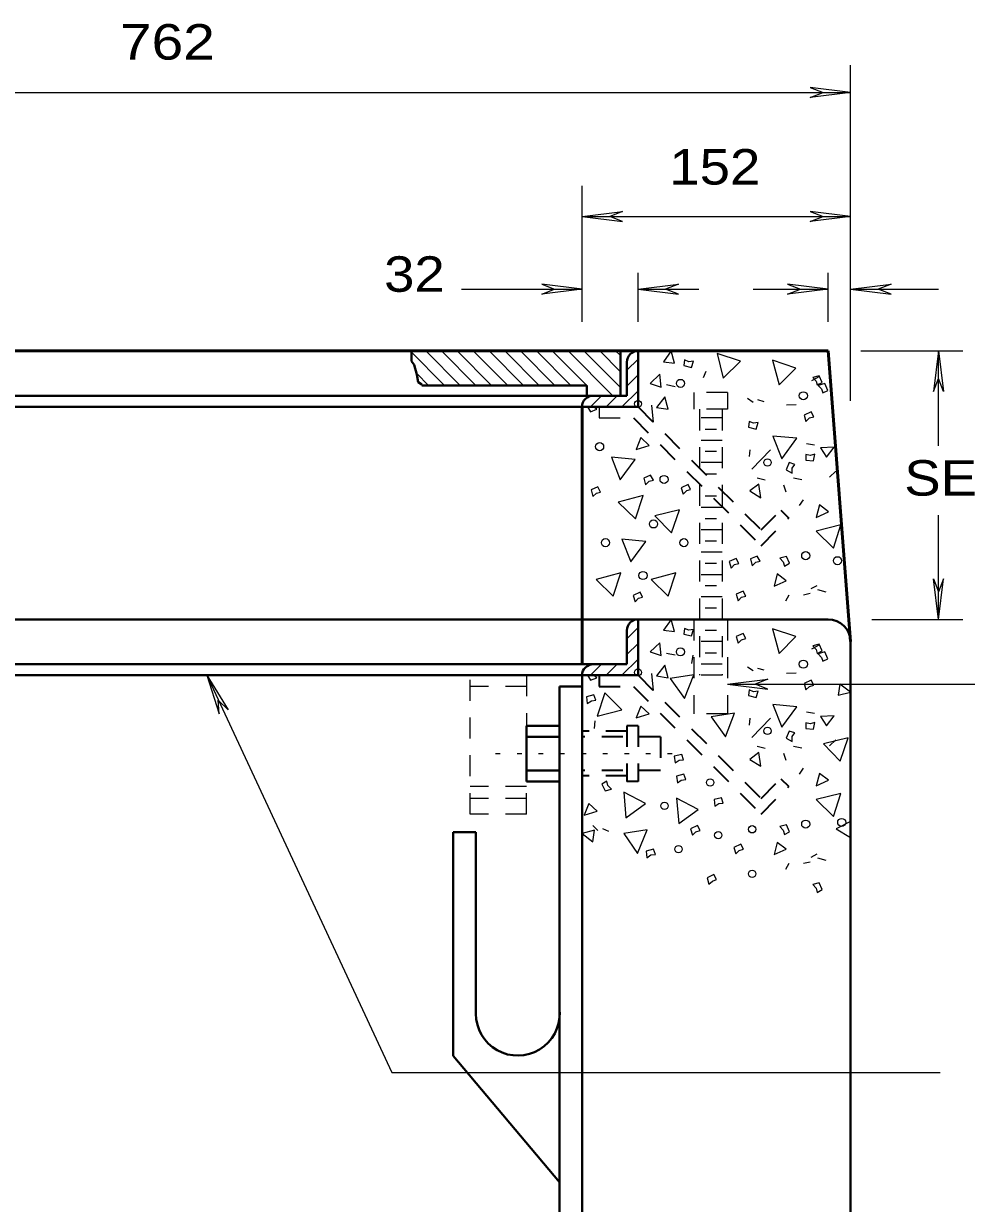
# Model space of a CAD drawing. Extents: x 312583 to 312853, y 144419 to 144586.
# Drawn here: x 312765.66 to 312785.86, y 144474.02 to 144499.29 of the extents above; entities that cross this region are included whole.
import ezdxf

# ---------------------------------------------------------------- set-up
doc = ezdxf.new("R2010")
doc.units = 0
doc.header["$LTSCALE"] = 0.3
doc.header["$PDMODE"] = 32
doc.header["$PDSIZE"] = 0.15
doc.linetypes.add('DOTTED', pattern=[1.5, 0.3, -1.2])
doc.linetypes.add('SHORT_DASHED', pattern=[2.7, 1.5, -1.2])
doc.layers.add('1', color=7, linetype='Continuous', lineweight=40)
doc.layers.add('2', color=7, linetype='Continuous', lineweight=13)

msp = doc.modelspace()

# ---------------------------------------------------------------- linework, layer by layer
at = {"layer": '1', "lineweight": 53}
for p, q in [((312755.1014, 144492.2754), (312782.893, 144492.2754)), ((312783.376, 144486.0501), (312782.893, 144492.2754)), ((312777.626, 144491.0794), (312777.626, 144485.5671))]:
    msp.add_line(p, q, dxfattribs=at)
at = {"layer": '1'}
for p, q in [((312778.4464, 144492.2754), (312778.4464, 144491.3171)), ((312778.822, 144492.2754), (312778.822, 144491.0794)), ((312778.5844, 144492.0377), (312778.5844, 144491.3171)), ((312774.1914, 144491.5394), (312777.7257, 144491.5394)), ((312777.7257, 144491.5394), (312777.7257, 144491.3171)), ((312759.4177, 144491.3171), (312778.5844, 144491.3171)), ((312759.18, 144491.0794), (312778.822, 144491.0794)), ((312755.1014, 144486.5254), (312782.893, 144486.5254)), ((312778.5844, 144486.2877), (312778.5844, 144485.5671)), ((312778.822, 144486.5254), (312778.822, 144485.3294)), ((312783.376, 144486.0501), (312783.376, 144443.4004)), ((312759.295, 144485.5671), (312778.5844, 144485.5671)), ((312759.0574, 144485.3294), (312778.822, 144485.3294)), ((312777.626, 144485.3294), (312777.626, 144443.4004)), ((312777.626, 144485.0917), (312777.143, 144485.0917)), ((312777.143, 144485.0917), (312777.143, 144454.4251)), ((312776.43, 144484.2484), (312776.43, 144483.0524)), ((312777.143, 144484.2484), (312776.43, 144484.2484)), ((312777.143, 144484.0107), (312776.43, 144484.0107)), ((312777.143, 144483.2901), (312776.43, 144483.2901)), ((312777.143, 144483.0524), (312776.43, 144483.0524)), ((312774.866, 144481.9714), (312774.866, 144477.1797)), ((312775.349, 144481.9714), (312774.866, 144481.9714)), ((312775.349, 144481.9714), (312775.349, 144478.0844)), ((312777.143, 144474.4734), (312774.866, 144477.1797))]:
    msp.add_line(p, q, dxfattribs=at)
at = {"layer": '1', "linetype": 'SHORT_DASHED', "lineweight": 25}
for p, q in [((312780.018, 144491.3861), (312780.018, 144491.0257)), ((312780.7387, 144491.3861), (312780.018, 144491.3861)), ((312780.7387, 144491.3861), (312780.7387, 144491.0257)), ((312777.9864, 144491.0794), (312777.9864, 144490.8417)), ((312777.9864, 144490.8417), (312778.7224, 144490.8417)), ((312780.7387, 144491.0257), (312780.018, 144491.0257)), ((312780.1407, 144491.0257), (312780.1407, 144485.3294)), ((312780.6237, 144490.8417), (312780.1407, 144490.8417)), ((312780.6237, 144491.0257), (312780.6237, 144485.3294)), ((312780.501, 144490.5964), (312780.2634, 144490.5964)), ((312780.6237, 144490.3587), (312780.1407, 144490.3587)), ((312780.501, 144490.1211), (312780.2634, 144490.1211)), ((312780.6237, 144489.8834), (312780.1407, 144489.8834)), ((312780.501, 144489.6381), (312780.2634, 144489.6381)), ((312780.501, 144489.1627), (312780.2634, 144489.1627)), ((312780.6237, 144488.9251), (312780.1407, 144488.9251)), ((312780.501, 144488.6797), (312780.2634, 144488.6797)), ((312780.6237, 144488.4421), (312780.1407, 144488.4421)), ((312780.501, 144488.2044), (312780.2634, 144488.2044)), ((312780.6237, 144487.9667), (312780.1407, 144487.9667)), ((312780.501, 144487.7214), (312780.2634, 144487.7214)), ((312780.6237, 144487.4837), (312780.1407, 144487.4837)), ((312780.501, 144487.2461), (312780.2634, 144487.2461)), ((312780.6237, 144487.0084), (312780.1407, 144487.0084)), ((312780.501, 144486.7631), (312780.2634, 144486.7631)), ((312780.018, 144486.5254), (312780.018, 144484.5014)), ((312780.6237, 144486.5254), (312780.1407, 144486.5254)), ((312780.501, 144486.2877), (312780.2634, 144486.2877)), ((312780.7387, 144486.5254), (312780.7387, 144484.5014)), ((312780.6237, 144486.0501), (312780.1407, 144486.0501)), ((312780.501, 144485.8047), (312780.2634, 144485.8047)), ((312780.6237, 144485.5671), (312780.1407, 144485.5671)), ((312775.2264, 144482.3547), (312775.2264, 144485.3294)), ((312776.43, 144485.3294), (312776.43, 144484.2484)), ((312780.6237, 144485.3294), (312780.1407, 144485.3294)), ((312776.43, 144485.0917), (312775.2264, 144485.0917)), ((312780.7387, 144484.5014), (312780.018, 144484.5014)), ((312776.43, 144482.3547), (312776.43, 144483.0524)), ((312776.43, 144482.9451), (312775.2264, 144482.9451)), ((312776.43, 144482.6921), (312775.2264, 144482.6921)), ((312776.43, 144482.3547), (312775.2264, 144482.3547))]:
    msp.add_line(p, q, dxfattribs=at)
at = {"layer": '1', "linetype": 'SHORT_DASHED', "lineweight": 35}
for p, q in [((312778.7224, 144490.8417), (312781.4594, 144488.1047)), ((312778.822, 144491.0794), (312781.4594, 144488.4421)), ((312781.4594, 144488.4421), (312781.881, 144488.8637)), ((312781.881, 144488.8637), (312782.0497, 144488.6951)), ((312781.4594, 144488.1047), (312782.0497, 144488.6951)), ((312777.9864, 144485.3294), (312777.9864, 144485.0917)), ((312778.822, 144485.3294), (312781.4594, 144482.6921)), ((312777.9864, 144485.0917), (312778.7224, 144485.0917)), ((312778.7224, 144485.0917), (312781.4594, 144482.3547)), ((312778.5844, 144484.1334), (312777.626, 144484.1334)), ((312779.305, 144484.0107), (312777.626, 144484.0107)), ((312778.5844, 144484.2484), (312778.5844, 144483.0524)), ((312778.822, 144484.2484), (312778.5844, 144484.2484)), ((312778.822, 144484.2484), (312778.822, 144483.0524)), ((312779.305, 144484.0107), (312779.305, 144483.2901)), ((312779.305, 144483.2901), (312777.626, 144483.2901)), ((312778.5844, 144483.1751), (312777.626, 144483.1751)), ((312778.822, 144483.0524), (312778.5844, 144483.0524)), ((312781.4594, 144482.6921), (312781.881, 144483.1137)), ((312781.881, 144483.1137), (312782.0497, 144482.9451)), ((312781.4594, 144482.3547), (312782.0497, 144482.9451))]:
    msp.add_line(p, q, dxfattribs=at)
at = {"layer": '1', "linetype": 'DOTTED', "lineweight": 13}
msp.add_line((312775.7707, 144483.6504), (312779.5964, 144483.6504), dxfattribs=at)
at = {"layer": '1'}
msp.add_lwpolyline([(312773.969, 144492.2601), (312773.969, 144492.0607), (312774.0304, 144491.9764), (312774.084, 144491.7694), (312774.1147, 144491.6084), (312774.1914, 144491.5547)], dxfattribs=at)
for centre, radius, start, end in [((312778.822, 144492.0368), 0.2396, 90, 180), ((312777.8637, 144491.0784), 0.2396, 90, 180), ((312778.822, 144486.2868), 0.2396, 90, 180), ((312782.8949, 144486.0472), 0.4792, 0, 90), ((312777.8637, 144485.3284), 0.2396, 90, 180), ((312776.247, 144478.081), 0.8984, 180.03057, 1.87136)]:
    msp.add_arc(centre, radius, start, end, dxfattribs=at)
at = {"layer": '2'}
for p, q in [((312783.376, 144491.2097), (312783.376, 144498.4011)), ((312782.5097, 144497.9181), (312782.7857, 144497.8107)), ((312783.376, 144497.8107), (312782.5097, 144497.9181)), ((312754.5647, 144497.8107), (312783.376, 144497.8107)), ((312782.5097, 144497.7034), (312782.7857, 144497.8107)), ((312783.376, 144497.8107), (312782.5097, 144497.7034)), ((312777.626, 144492.8964), (312777.626, 144495.8097)), ((312777.626, 144495.1581), (312778.4924, 144495.2654)), ((312777.626, 144495.1581), (312783.376, 144495.1581)), ((312777.626, 144495.1581), (312778.4924, 144495.0507)), ((312778.4924, 144495.2654), (312778.2164, 144495.1581)), ((312778.4924, 144495.0507), (312778.2164, 144495.1581)), ((312782.5097, 144495.2654), (312782.7857, 144495.1581)), ((312783.376, 144495.1581), (312782.5097, 144495.2654)), ((312782.5097, 144495.0507), (312782.7857, 144495.1581)), ((312783.376, 144495.1581), (312782.5097, 144495.0507)), ((312778.822, 144492.8964), (312778.822, 144493.9467)), ((312782.893, 144492.8964), (312782.893, 144493.9467)), ((312776.7597, 144493.7091), (312777.0357, 144493.6017)), ((312777.626, 144493.6017), (312776.7597, 144493.7091)), ((312778.822, 144493.6017), (312779.6884, 144493.7091)), ((312779.6884, 144493.7091), (312779.4124, 144493.6017)), ((312782.0267, 144493.7091), (312782.3027, 144493.6017)), ((312782.893, 144493.6017), (312782.0267, 144493.7091)), ((312783.376, 144493.6017), (312784.2424, 144493.7091)), ((312784.2424, 144493.7091), (312783.9664, 144493.6017)), ((312775.0424, 144493.6017), (312777.626, 144493.6017)), ((312776.7597, 144493.4944), (312777.0357, 144493.6017)), ((312777.626, 144493.6017), (312776.7597, 144493.4944)), ((312778.822, 144493.6017), (312780.1254, 144493.6017)), ((312778.822, 144493.6017), (312779.6884, 144493.4944)), ((312779.6884, 144493.4944), (312779.4124, 144493.6017)), ((312781.2907, 144493.6017), (312782.893, 144493.6017)), ((312782.0267, 144493.4944), (312782.3027, 144493.6017)), ((312782.893, 144493.6017), (312782.0267, 144493.4944)), ((312783.376, 144493.6017), (312785.262, 144493.6017)), ((312783.376, 144493.6017), (312784.2424, 144493.4944)), ((312784.2424, 144493.4944), (312783.9664, 144493.6017)), ((312773.9384, 144492.2754), (312774.6744, 144491.5394)), ((312774.2757, 144492.2754), (312775.0117, 144491.5394)), ((312774.613, 144492.2754), (312775.349, 144491.5394)), ((312774.9504, 144492.2754), (312775.6864, 144491.5394)), ((312775.2877, 144492.2754), (312776.0314, 144491.5394)), ((312775.6327, 144492.2754), (312776.3687, 144491.5394)), ((312775.97, 144492.2754), (312776.706, 144491.5394)), ((312776.3074, 144492.2754), (312777.0434, 144491.5394)), ((312776.6447, 144492.2754), (312777.3807, 144491.5394)), ((312776.982, 144492.2754), (312777.7257, 144491.5394)), ((312777.327, 144492.2754), (312778.2854, 144491.3171)), ((312777.6644, 144492.2754), (312778.4464, 144491.4934)), ((312778.0017, 144492.2754), (312778.4464, 144491.8307)), ((312778.339, 144492.2754), (312778.4464, 144492.1757)), ((312778.5844, 144491.8614), (312778.822, 144492.0991)), ((312783.5984, 144492.2754), (312785.7834, 144492.2754)), ((312785.262, 144492.2754), (312785.1547, 144491.4091)), ((312785.262, 144490.2437), (312785.262, 144492.2754)), ((312785.262, 144492.2754), (312785.3694, 144491.4091)), ((312780.225, 144491.7081), (312780.2787, 144491.8461)), ((312774.084, 144491.7924), (312774.337, 144491.5394)), ((312778.5844, 144491.5241), (312778.822, 144491.7617)), ((312782.709, 144491.7311), (312782.5404, 144491.6391)), ((312785.1547, 144491.4091), (312785.262, 144491.6851)), ((312785.3694, 144491.4091), (312785.262, 144491.6851)), ((312778.477, 144491.0794), (312778.822, 144491.4244)), ((312779.4354, 144491.5547), (312779.6194, 144491.5164)), ((312777.8024, 144491.0794), (312778.04, 144491.3171)), ((312778.1397, 144491.0794), (312778.3774, 144491.3171)), ((312779.1517, 144490.7497), (312779.121, 144491.1177)), ((312781.168, 144491.2634), (312781.2907, 144491.1791)), ((312781.3827, 144491.2327), (312781.5207, 144491.1944)), ((312782.2107, 144491.1254), (312782.0037, 144491.1177)), ((312781.214, 144490.1594), (312781.2064, 144490.0137)), ((312781.26, 144489.7454), (312781.6587, 144490.1594)), ((312782.6017, 144490.2591), (312782.433, 144490.2897)), ((312782.9237, 144489.5691), (312783.0617, 144489.6994)), ((312781.375, 144489.5614), (312781.5437, 144489.5154)), ((312781.996, 144489.2547), (312781.9424, 144489.4004)), ((312782.1494, 144489.5614), (312782.3334, 144489.5231)), ((312782.3564, 144489.0861), (312782.272, 144488.9634)), ((312785.262, 144486.5254), (312785.262, 144488.7564)), ((312785.1547, 144487.3917), (312785.262, 144487.1157)), ((312785.262, 144486.5254), (312785.1547, 144487.3917)), ((312785.3694, 144487.3917), (312785.262, 144487.1157)), ((312785.262, 144486.5254), (312785.3694, 144487.3917)), ((312782.0497, 144487.0467), (312781.9807, 144486.9164)), ((312782.364, 144487.0544), (312782.5097, 144487.0851)), ((312782.5327, 144487.1847), (312782.663, 144487.2537)), ((312782.8547, 144487.1081), (312782.6707, 144487.1617)), ((312778.5844, 144486.1114), (312778.822, 144486.3491)), ((312783.8284, 144486.5254), (312785.7834, 144486.5254)), ((312778.5844, 144485.7741), (312778.822, 144486.0117)), ((312779.4354, 144485.8047), (312779.6194, 144485.7664)), ((312782.709, 144485.9811), (312782.5404, 144485.8891)), ((312777.8024, 144485.3294), (312778.04, 144485.5671)), ((312778.1397, 144485.3294), (312778.3774, 144485.5671)), ((312778.477, 144485.3294), (312778.822, 144485.6744)), ((312779.995, 144485.7587), (312779.9644, 144485.5824)), ((312769.5837, 144485.3294), (312769.852, 144484.5014)), ((312769.5837, 144485.3294), (312770.0437, 144484.5857)), ((312779.1517, 144484.9997), (312779.121, 144485.3677)), ((312781.168, 144485.5134), (312781.2907, 144485.4291)), ((312781.3827, 144485.4827), (312781.5207, 144485.4444)), ((312782.2107, 144485.3754), (312782.0037, 144485.3677)), ((312780.7387, 144485.1377), (312781.605, 144485.2451)), ((312780.7387, 144485.1377), (312789.494, 144485.1377)), ((312780.7387, 144485.1377), (312781.605, 144485.0304)), ((312781.605, 144485.2451), (312781.329, 144485.1377)), ((312781.605, 144485.0304), (312781.329, 144485.1377)), ((312769.852, 144484.5014), (312769.829, 144484.7927)), ((312770.0437, 144484.5857), (312769.829, 144484.7927)), ((312782.6017, 144484.5091), (312782.433, 144484.5397)), ((312777.8867, 144484.1871), (312777.902, 144484.3557)), ((312781.214, 144484.4094), (312781.2064, 144484.2637)), ((312781.26, 144483.9954), (312781.6587, 144484.4094)), ((312781.375, 144483.8114), (312781.5437, 144483.7654)), ((312782.1494, 144483.8114), (312782.3334, 144483.7731)), ((312782.9237, 144483.8191), (312783.0617, 144483.9494)), ((312781.996, 144483.5047), (312781.9424, 144483.6504)), ((312782.3564, 144483.3361), (312782.272, 144483.2134)), ((312777.856, 144482.1094), (312777.9634, 144482.0021)), ((312778.063, 144482.0481), (312778.1934, 144481.9867)), ((312782.5327, 144481.4347), (312782.663, 144481.5037)), ((312782.0497, 144481.2967), (312781.9807, 144481.1664)), ((312782.364, 144481.3044), (312782.5097, 144481.3351)), ((312782.8547, 144481.3581), (312782.6707, 144481.4117))]:
    msp.add_line(p, q, dxfattribs=at)
for points in [[(312779.3664, 144492.0454), (312779.604, 144492.0147), (312779.535, 144492.2754)], [(312780.6467, 144491.6927), (312781.0147, 144492.0607), (312780.5164, 144492.2217)], [(312779.9107, 144492.0454), (312779.8187, 144492.0837), (312779.8034, 144491.9611), (312779.9644, 144491.9227), (312780.0104, 144492.0607)], [(312781.8427, 144491.5471), (312782.203, 144491.9074), (312781.7047, 144492.0761)], [(312779.0827, 144491.5777), (312779.3204, 144491.5011), (312779.2897, 144491.7771)], [(312782.64, 144491.6314), (312782.663, 144491.5471), (312782.7704, 144491.6007), (312782.7014, 144491.7464), (312782.5634, 144491.7081)], [(312782.755, 144491.4627), (312782.778, 144491.3784), (312782.8854, 144491.4321), (312782.824, 144491.5777), (312782.6784, 144491.5394)], [(312779.2207, 144491.0641), (312779.466, 144491.0257), (312779.397, 144491.2941)], [(312782.4944, 144490.8417), (312782.5864, 144490.8647), (312782.5327, 144490.9721), (312782.3794, 144490.9031), (312782.4177, 144490.7651)], [(312781.2984, 144490.7267), (312781.2064, 144490.7651), (312781.191, 144490.6424), (312781.352, 144490.6041), (312781.398, 144490.7421)], [(312779.0597, 144490.2514), (312778.8834, 144490.4201), (312778.7837, 144490.1671)], [(312782.226, 144490.4047), (312781.7124, 144490.4507), (312781.904, 144489.9677)], [(312782.732, 144490.1977), (312782.8624, 144489.9984), (312783.0234, 144490.2131)], [(312778.7607, 144489.9524), (312778.2547, 144489.9984), (312778.4387, 144489.5154)], [(312782.1264, 144489.7684), (312782.18, 144489.8451), (312782.0574, 144489.8834), (312781.996, 144489.7301), (312782.1264, 144489.6611)], [(312782.5097, 144490.0367), (312782.4177, 144490.0597), (312782.4177, 144489.9371), (312782.5787, 144489.9217), (312782.6094, 144490.0674)], [(312779.0597, 144489.4847), (312779.1517, 144489.5077), (312779.0904, 144489.6151), (312778.9447, 144489.5537), (312778.983, 144489.4081)], [(312777.9327, 144489.2317), (312778.017, 144489.2547), (312777.9634, 144489.3621), (312777.8177, 144489.3007), (312777.856, 144489.1551)], [(312779.8647, 144489.2854), (312779.949, 144489.3084), (312779.8954, 144489.4157), (312779.7497, 144489.3467), (312779.788, 144489.2087)], [(312781.4134, 144489.4234), (312781.214, 144489.2777), (312781.4517, 144489.1321)], [(312778.4004, 144489.0401), (312778.7684, 144488.6797), (312778.9294, 144489.1781)], [(312779.1824, 144488.7411), (312779.5427, 144488.3807), (312779.7114, 144488.8714)], [(312782.9007, 144488.8331), (312782.709, 144488.9787), (312782.64, 144488.7104)], [(312782.64, 144488.4191), (312783.008, 144488.0511), (312783.169, 144488.5494)], [(312778.9907, 144488.1967), (312778.477, 144488.2427), (312778.6687, 144487.7597)], [(312780.892, 144487.6984), (312780.984, 144487.7214), (312780.9227, 144487.8287), (312780.777, 144487.7674), (312780.8154, 144487.6217)], [(312781.3444, 144487.7521), (312781.4364, 144487.7751), (312781.375, 144487.8824), (312781.2294, 144487.8211), (312781.2677, 144487.6754)], [(312781.9347, 144487.7597), (312781.9577, 144487.6677), (312782.065, 144487.7291), (312782.0037, 144487.8747), (312781.858, 144487.8364)], [(312777.925, 144487.3841), (312778.293, 144487.0237), (312778.454, 144487.5221)], [(312779.1057, 144487.3841), (312779.466, 144487.0237), (312779.6347, 144487.5221)], [(312781.996, 144487.3534), (312781.8044, 144487.4991), (312781.7354, 144487.2384)], [(312778.8297, 144486.9777), (312778.9217, 144487.0007), (312778.868, 144487.1081), (312778.7147, 144487.0391), (312778.7607, 144486.9011)], [(312781.0377, 144487.0007), (312781.1297, 144487.0237), (312781.076, 144487.1311), (312780.9227, 144487.0697), (312780.9687, 144486.9241)], [(312779.3664, 144486.2954), (312779.604, 144486.2647), (312779.535, 144486.5254)], [(312779.9107, 144486.2954), (312779.8187, 144486.3337), (312779.8034, 144486.2111), (312779.9644, 144486.1727), (312780.0104, 144486.3107)], [(312781.8427, 144485.7971), (312782.203, 144486.1574), (312781.7047, 144486.3261)], [(312781.0377, 144486.0884), (312781.1297, 144486.1191), (312781.076, 144486.2264), (312780.9227, 144486.1574), (312780.9687, 144486.0194)], [(312779.0827, 144485.8277), (312779.3204, 144485.7511), (312779.2897, 144486.0271)], [(312782.64, 144485.8814), (312782.663, 144485.7971), (312782.7704, 144485.8507), (312782.7014, 144485.9964), (312782.5634, 144485.9581)], [(312782.755, 144485.7127), (312782.778, 144485.6284), (312782.8854, 144485.6821), (312782.824, 144485.8277), (312782.6784, 144485.7894)], [(312779.2207, 144485.3141), (312779.466, 144485.2757), (312779.397, 144485.5441)], [(312780.018, 144485.3371), (312779.512, 144485.2604), (312779.8187, 144484.8311)], [(312782.4944, 144485.0917), (312782.5864, 144485.1147), (312782.5327, 144485.2221), (312782.3794, 144485.1531), (312782.4177, 144485.0151)], [(312783.146, 144485.1377), (312783.1077, 144484.9001), (312783.376, 144484.9691)], [(312777.8254, 144484.7851), (312777.9174, 144484.7927), (312777.879, 144484.9077), (312777.718, 144484.8694), (312777.7334, 144484.7237)], [(312778.477, 144484.5857), (312778.109, 144484.9537), (312777.948, 144484.4554)], [(312781.2984, 144484.9767), (312781.2064, 144485.0151), (312781.191, 144484.8924), (312781.352, 144484.8541), (312781.398, 144484.9921)], [(312779.0597, 144484.5014), (312778.8834, 144484.6701), (312778.7837, 144484.4171)], [(312780.892, 144484.5167), (312780.386, 144484.4401), (312780.6927, 144484.0107)], [(312782.226, 144484.6547), (312781.7124, 144484.7007), (312781.904, 144484.2177)], [(312782.5097, 144484.2867), (312782.4177, 144484.3097), (312782.4177, 144484.1871), (312782.5787, 144484.1717), (312782.6094, 144484.3174)], [(312782.732, 144484.4477), (312782.8624, 144484.2484), (312783.0234, 144484.4631)], [(312782.1264, 144484.0184), (312782.18, 144484.0951), (312782.0574, 144484.1334), (312781.996, 144483.9801), (312782.1264, 144483.9111)], [(312782.7934, 144483.8574), (312783.1537, 144483.4894), (312783.3224, 144483.9877)], [(312779.7037, 144483.5124), (312779.7957, 144483.5201), (312779.7574, 144483.6351), (312779.5964, 144483.5967), (312779.6194, 144483.4511)], [(312781.4134, 144483.6734), (312781.214, 144483.5277), (312781.4517, 144483.3821)], [(312778.178, 144482.9681), (312778.155, 144483.0601), (312778.0477, 144482.9987), (312778.1167, 144482.8531), (312778.2547, 144482.8914)], [(312779.7497, 144483.0831), (312779.8494, 144483.0984), (312779.8034, 144483.2134), (312779.65, 144483.1674), (312779.6654, 144483.0217)], [(312782.9007, 144483.0831), (312782.709, 144483.2287), (312782.64, 144482.9604)], [(312778.5614, 144482.2781), (312778.983, 144482.5847), (312778.5154, 144482.8224)], [(312782.64, 144482.6691), (312783.008, 144482.3011), (312783.169, 144482.7994)], [(312777.948, 144482.4161), (312777.7717, 144482.5847), (312777.672, 144482.3317)], [(312779.696, 144482.1554), (312780.11, 144482.4544), (312779.65, 144482.6997)], [(312780.5547, 144482.5847), (312780.6467, 144482.5924), (312780.6084, 144482.7074), (312780.455, 144482.6691), (312780.4704, 144482.5234)], [(312777.856, 144481.7644), (312777.8867, 144482.0097), (312777.626, 144481.9407)], [(312779.0214, 144482.0174), (312778.5154, 144481.9407), (312778.8144, 144481.5114)], [(312780.064, 144481.9791), (312780.156, 144482.0021), (312780.0947, 144482.1094), (312779.949, 144482.0404), (312779.9874, 144481.9024)], [(312781.9347, 144482.0097), (312781.9577, 144481.9177), (312782.065, 144481.9791), (312782.0037, 144482.1247), (312781.858, 144482.0864)], [(312781.996, 144481.6034), (312781.8044, 144481.7491), (312781.7354, 144481.4884)], [(312779.098, 144481.4807), (312779.1977, 144481.4884), (312779.1517, 144481.6034), (312778.9984, 144481.5651), (312779.0137, 144481.4194)], [(312780.9917, 144481.5727), (312781.0837, 144481.6034), (312781.0224, 144481.7107), (312780.8767, 144481.6417), (312780.915, 144481.5037)], [(312780.4167, 144480.9211), (312780.501, 144480.9517), (312780.4474, 144481.0591), (312780.3017, 144480.9901), (312780.34, 144480.8521)], [(312782.64, 144480.7677), (312782.663, 144480.6757), (312782.7704, 144480.7371), (312782.7014, 144480.8827), (312782.5634, 144480.8444)]]:
    msp.add_lwpolyline(points, close=True, dxfattribs=at)
for points in [[(312777.741, 144491.0794), (312777.8024, 144490.9721), (312777.9404, 144491.0257), (312777.8714, 144491.0794)], [(312769.5837, 144485.3294), (312773.5474, 144476.8194), (312785.2927, 144476.8194)], [(312777.741, 144485.3294), (312777.8024, 144485.2221), (312777.9404, 144485.2757), (312777.8714, 144485.3294)], [(312783.376, 144482.1937), (312783.0694, 144482.0404), (312783.376, 144481.8564)]]:
    msp.add_lwpolyline(points, dxfattribs=at)
for centre, radius in [((312779.7313, 144491.5814), 0.0865), ((312782.3633, 144491.3167), 0.0865), ((312777.9996, 144490.2264), 0.0865), ((312781.5957, 144489.8873), 0.0784), ((312779.3796, 144489.5239), 0.0865), ((312779.1534, 144488.5704), 0.0865), ((312778.1251, 144488.1688), 0.0865), ((312779.806, 144488.1688), 0.0865), ((312782.4145, 144487.8909), 0.0865), ((312783.0946, 144487.7831), 0.0865), ((312778.9282, 144487.4664), 0.0865), ((312779.7313, 144485.8314), 0.0865), ((312782.3633, 144485.5667), 0.0865), ((312781.5957, 144484.1373), 0.0784), ((312780.3661, 144483.0333), 0.0784), ((312779.3877, 144482.532), 0.0784), ((312783.1857, 144482.1778), 0.0865), ((312781.2689, 144482.0299), 0.0784), ((312782.4145, 144482.1409), 0.0865), ((312780.5415, 144481.9043), 0.0784), ((312779.6886, 144481.6034), 0.0784), ((312781.2689, 144481.0763), 0.0784)]:
    msp.add_circle(centre, radius, dxfattribs=at)
for p in [(312778.822, 144491.1407), (312778.822, 144485.3907)]:
    msp.add_point(p, dxfattribs=at)

# ---------------------------------------------------------------- texts
for s, width, p in [('762 ', 1.2, (312767.7239, 144498.5167)), ('152 ', 1.15, (312779.4925, 144495.8404)), ('32 ', 1.15, (312773.3822, 144493.5433)), ('SEE NOTE #4', 1.15, (312784.526, 144489.1765))]:
    msp.add_text(s, height=0.76, dxfattribs=dict(at, width=width)).set_placement(p)

doc.saveas('drawing.dxf')
